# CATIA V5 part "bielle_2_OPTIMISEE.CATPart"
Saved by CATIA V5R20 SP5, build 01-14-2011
Part number: bielle_2
Bounding box of the stored display mesh (mm): x 0 to 15, y -29.989 to 29.989, z -29.951 to 110
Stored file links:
  U:\2A\IAO\ThinkMotion\CAO\bielle_2_OPTIMISEE.CATPart
  U:\2A\IAO\ThinkMotion\CAO\MECANISME 1517.CATProduct
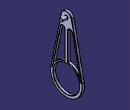
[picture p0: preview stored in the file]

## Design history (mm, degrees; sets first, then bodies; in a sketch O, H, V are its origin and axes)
Set1
  Plane1 "Plan_ref": linked copy from another document
  Point1: linked copy from another document
  Point2: linked copy from another document
Set2
  Plane2: type Offset, RefPlane yz-plane, Offset 2.5
Body1 (main body)
  Sketch1 on Plane1, origin (0, 0, 0), H (0, 1, 0), V (0, 0, 1)
    circle A1 centre (0, 0) radius 25
    point P1 (0, 0)
    reference projected point E1 (0, 0) from Point1
    arc A2 centre (0, 100) radius 10 from (-9.798, 102) to (9.798, 102) cw
    point P6 (0, 100)
    reference projected point E2 (0, 100) from Point2
    arc A3 centre (0, 0) radius 30 from (-29.3939, 6) to (29.3939, 6) ccw
    point P7 (0, 0)
    reference projected point E3 (0, 0) from Point1
    line L1 (29.3939, 6) -> (9.798, 102)
    line L2 (-29.3939, 6) -> (-9.798, 102)
    radius A1 = 25
    distance A3 A1 = 5
    radius A2 = 10
    coincidence: P1 V, P1 E1, P6 E2, P7 E3
    tangency: L1 A3, A2 L1, A2 L2, L2 A3
  Pad1: profile Sketch1, direction (1, 0, 0), length 5
  Sketch2 on Plane1, origin (0, 0, 0), H (0, 1, 0), V (0, 0, 1)
    circle A1 centre (0, 100) radius 3
    point P1 (0, 100)
    reference projected point E1 (0, 100) from Point2
    radius A1 = 3
    coincidence: P1 V, P1 E1
  Pad2: profile Sketch2, direction (1, 0, 0), length 15
  Sketch3 on end face of Pad1, origin (5, 0, 0), H (0, 1, 0), V (0, 0, 1)
    construction line L1 through (0, 25.8423) direction (0, 1)
    line L2 (-3, 80) -> (-3, 27.8388)
    line L3 (3, 80) -> (3, 27.8388)
    line L4 (-11.0606, 80.8143) -> (-24.9712, 12.6664)
    line L5 (11.0606, 80.8143) -> (24.9712, 12.6664)
    arc A1 centre (7.0714, 80) radius 4.0714 from (3, 80) to (11.0606, 80.8143) cw
    point P1 (11.0606, 80.8143)
    point P2 (11.0606, 80.8143)
    arc A2 centre (-7.0714, 80) radius 4.0714 from (-3, 80) to (-11.0606, 80.8143) ccw
    point P3 (3, 27.8388)
    point P4 (0, 0)
    point P5 (0, 0)
    point P6 (3, 27.8388)
    arc A3 centre (0, 0) radius 28 from (24.9712, 12.6664) to (3, 27.8388) ccw
    construction line L6 through (-14.5518, 0) direction (1, 0)
    construction line L7 (23.3008, 0) -> (-47.7625, 0)
    point P7 (7.0714, 80)
    axis line L8 (82.1694, 80) -> (-31.6946, 80)
    point P8 (-7.0714, 80)
    point P15 (0, 0)
    arc A4 centre (0, 0) radius 28 from (-3, 27.8388) to (-24.9712, 12.6664) ccw
    reference projected line E1 (29.3939, 6) -> (9.798, 102) from edge [face of Pad1 from Sketch1.L1 | end face of Pad1]
    reference projected circle E2 centre (0, 0) radius 25 from edge [end face of Pad1 | face of Pad1 from Sketch1.A1]
    reference projected line E3 (-9.798, 102) -> (-29.3939, 6) from edge [face of Pad1 from Sketch1.L2 | end face of Pad1]
    reference projected line E4 (-9.798, 102) -> (-29.3939, 6) from edge [face of Pad1 from Sketch1.L2 | end face of Pad1]
    distance L3 L1 = 3
    distance L8 L7 = 80
    distance L2 L3 = 6
    distance L5 E1 = 3
    distance A3 E2 = 3
    distance L4 E4 = 3
    vertical: L2 L1, L3 L1
    tangency: A1 L3, A1 L5, A2 L4, A2 L2
    coincidence: P2 P1, P3 L3, P5 P4, P3 P6, L7 L6, L8 P7, P8 L8, L7 H, A4 A3, L1 V, P15 O
    parallelism: E3 L4
  Pocket1: profile Sketch3, direction (-1, 0, 0), through (limit type 3)
  Fillet1: radius 0.5, on end face of Pad1; face of Pad2; face of Pad2 from Sketch2.A1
